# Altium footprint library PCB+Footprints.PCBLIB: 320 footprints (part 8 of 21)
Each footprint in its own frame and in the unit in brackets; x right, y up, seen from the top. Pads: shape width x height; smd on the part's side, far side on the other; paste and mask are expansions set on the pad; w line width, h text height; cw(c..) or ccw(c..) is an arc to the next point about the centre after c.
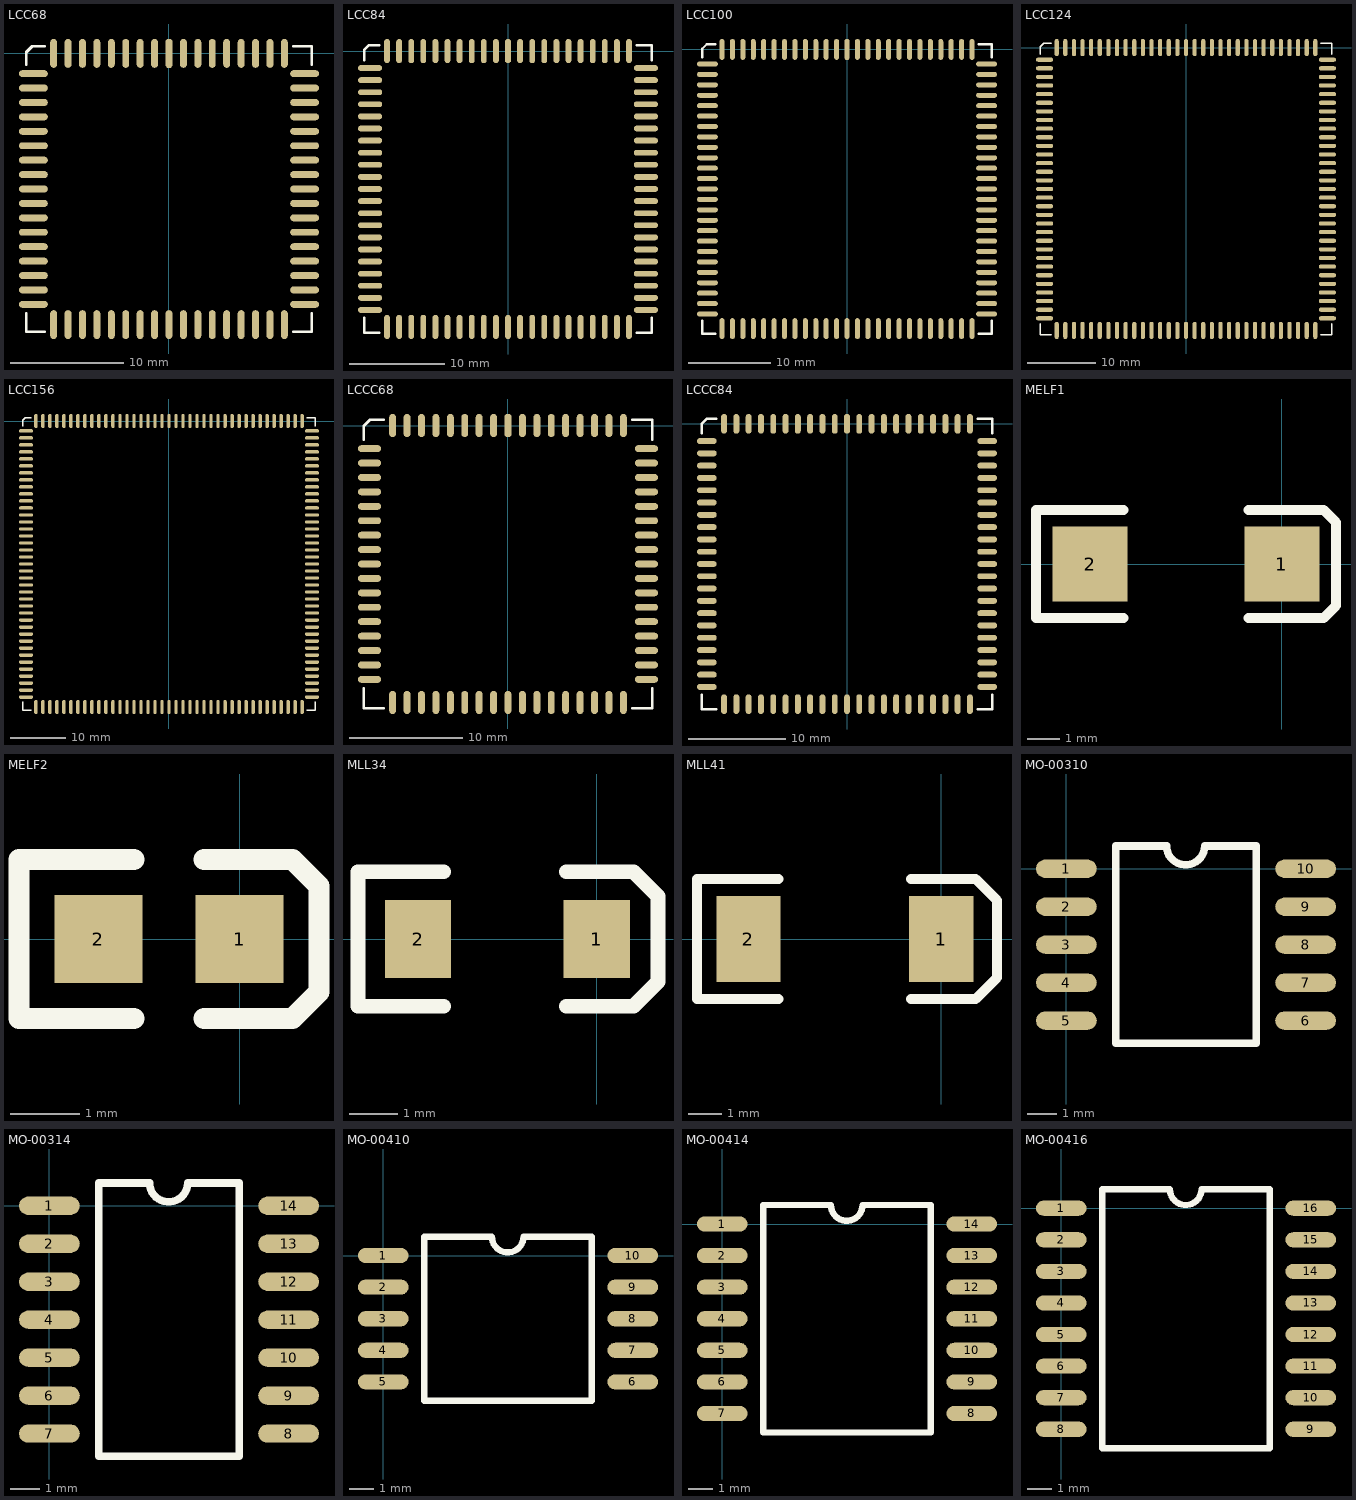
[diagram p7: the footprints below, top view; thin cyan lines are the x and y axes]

## LCC68 [mil]
pads (68):
  oct 24x100 smd: 1(0,0)
  oval 24x100 smd: 2(-50,0) 3(-100,0) 4(-150,0) 5(-200,0) 6(-250,0) 7(-300,0) 8(-350,0) 9(-400,0) 27(-400,-940) 28(-350,-940) 29(-300,-940) 30(-250,-940) 31(-200,-940) 32(-150,-940) 33(-100,-940) 34(-50,-940) 35(0,-940) 36(50,-940) 37(100,-940) 38(150,-940) 39(200,-940) 40(250,-940) 41(300,-940) 42(350,-940) 43(400,-940) 61(400,0) 62(350,0) 63(300,0) 64(250,0) 65(200,0) 66(150,0) 67(100,0) 68(50,0)
  oval 100x24 smd: 10(-470,-70) 11(-470,-120) 12(-470,-170) 13(-470,-220) 14(-470,-270) 15(-470,-320) 16(-470,-370) 17(-470,-420) 18(-470,-470) 19(-470,-520) 20(-470,-570) 21(-470,-620) 22(-470,-670) 23(-470,-720) 24(-470,-770) 25(-470,-820) 26(-470,-870) 44(470,-870) 45(470,-820) 46(470,-770) 47(470,-720) 48(470,-670) 49(470,-620) 50(470,-570) 51(470,-520) 52(470,-470) 53(470,-420) 54(470,-370) 55(470,-320) 56(470,-270) 57(470,-220) 58(470,-170) 59(470,-120) 60(470,-70)
TopOverlay:
  lines w10: -495,-902 -495,-965 -432,-965 ; -495,-38 -495,4 -474,25 -432,25 ; 432,-965 495,-965 495,-902 ; 432,25 495,25 495,-38

## LCC84 [mil]
pads (84):
  oct 24x100 smd: 1(0,0)
  oval 24x100 smd: 2(-50,0) 3(-100,0) 4(-150,0) 5(-200,0) 6(-250,0) 7(-300,0) 8(-350,0) 9(-400,0) 10(-450,0) 11(-500,0) 33(-500,-1140) 34(-450,-1140) 35(-400,-1140) 36(-350,-1140) 37(-300,-1140) 38(-250,-1140) 39(-200,-1140) 40(-150,-1140) 41(-100,-1140) 42(-50,-1140) 43(0,-1140) 44(50,-1140) 45(100,-1140) 46(150,-1140) 47(200,-1140) 48(250,-1140) 49(300,-1140) 50(350,-1140) 51(400,-1140) 52(450,-1140) 53(500,-1140) 75(500,0) 76(450,0) 77(400,0) 78(350,0) 79(300,0) 80(250,0) 81(200,0) 82(150,0) 83(100,0) 84(50,0)
  oval 100x24 smd: 12(-570,-70) 13(-570,-120) 14(-570,-170) 15(-570,-220) 16(-570,-270) 17(-570,-320) 18(-570,-370) 19(-570,-420) 20(-570,-470) 21(-570,-520) 22(-570,-570) 23(-570,-620) 24(-570,-670) 25(-570,-720) 26(-570,-770) 27(-570,-820) 28(-570,-870) 29(-570,-920) 30(-570,-970) 31(-570,-1020) 32(-570,-1070) 54(570,-1070) 55(570,-1020) 56(570,-970) 57(570,-920) 58(570,-870) 59(570,-820) 60(570,-770) 61(570,-720) 62(570,-670) 63(570,-620) 64(570,-570) 65(570,-520) 66(570,-470) 67(570,-420) 68(570,-370) 69(570,-320) 70(570,-270) 71(570,-220) 72(570,-170) 73(570,-120) 74(570,-70)
TopOverlay:
  lines w10: -595,-1102 -595,-1165 -532,-1165 ; -595,-38 -595,4 -574,25 -532,25 ; 532,-1165 595,-1165 595,-1102 ; 532,25 595,25 595,-38

## LCC100 [mil]
pads (100):
  oct 24x100 smd: 1(0,0)
  oval 24x100 smd: 2(-50,0) 3(-100,0) 4(-150,0) 5(-200,0) 6(-250,0) 7(-300,0) 8(-350,0) 9(-400,0) 10(-450,0) 11(-500,0) 12(-550,0) 13(-600,0) 39(-600,-1340) 40(-550,-1340) 41(-500,-1340) 42(-450,-1340) 43(-400,-1340) 44(-350,-1340) 45(-300,-1340) 46(-250,-1340) 47(-200,-1340) 48(-150,-1340) 49(-100,-1340) 50(-50,-1340) 51(0,-1340) 52(50,-1340) 53(100,-1340) 54(150,-1340) 55(200,-1340) 56(250,-1340) 57(300,-1340) 58(350,-1340) 59(400,-1340) 60(450,-1340) 61(500,-1340) 62(550,-1340) 63(600,-1340) 89(600,0) 90(550,0) 91(500,0) 92(450,0) 93(400,0) 94(350,0) 95(300,0) 96(250,0) 97(200,0) 98(150,0) 99(100,0) 100(50,0)
  oval 100x24 smd: 14(-670,-70) 15(-670,-120) 16(-670,-170) 17(-670,-220) 18(-670,-270) 19(-670,-320) 20(-670,-370) 21(-670,-420) 22(-670,-470) 23(-670,-520) 24(-670,-570) 25(-670,-620) 26(-670,-670) 27(-670,-720) 28(-670,-770) 29(-670,-820) 30(-670,-870) 31(-670,-920) 32(-670,-970) 33(-670,-1020) 34(-670,-1070) 35(-670,-1120) 36(-670,-1170) 37(-670,-1220) 38(-670,-1270) 64(670,-1270) 65(670,-1220) 66(670,-1170) 67(670,-1120) 68(670,-1070) 69(670,-1020) 70(670,-970) 71(670,-920) 72(670,-870) 73(670,-820) 74(670,-770) 75(670,-720) 76(670,-670) 77(670,-620) 78(670,-570) 79(670,-520) 80(670,-470) 81(670,-420) 82(670,-370) 83(670,-320) 84(670,-270) 85(670,-220) 86(670,-170) 87(670,-120) 88(670,-70)
TopOverlay:
  lines w10: -695,-1302 -695,-1365 -632,-1365 ; -695,-38 -695,4 -674,25 -632,25 ; 632,-1365 695,-1365 695,-1302 ; 632,25 695,25 695,-38

## LCC124 [mil]
pads (124):
  oct 24x100 smd: 1(0,0)
  oval 24x100 smd: 2(-50,0) 3(-100,0) 4(-150,0) 5(-200,0) 6(-250,0) 7(-300,0) 8(-350,0) 9(-400,0) 10(-450,0) 11(-500,0) 12(-550,0) 13(-600,0) 14(-650,0) 15(-700,0) 16(-750,0) 48(-750,-1640) 49(-700,-1640) 50(-650,-1640) 51(-600,-1640) 52(-550,-1640) 53(-500,-1640) 54(-450,-1640) 55(-400,-1640) 56(-350,-1640) 57(-300,-1640) 58(-250,-1640) 59(-200,-1640) 60(-150,-1640) 61(-100,-1640) 62(-50,-1640) 63(0,-1640) 64(50,-1640) 65(100,-1640) 66(150,-1640) 67(200,-1640) 68(250,-1640) 69(300,-1640) 70(350,-1640) 71(400,-1640) 72(450,-1640) 73(500,-1640) 74(550,-1640) 75(600,-1640) 76(650,-1640) 77(700,-1640) 78(750,-1640) 110(750,0) 111(700,0) 112(650,0) 113(600,0) 114(550,0) 115(500,0) 116(450,0) 117(400,0) 118(350,0) 119(300,0) 120(250,0) 121(200,0) 122(150,0) 123(100,0) 124(50,0)
  oval 100x24 smd: 17(-820,-70) 18(-820,-120) 19(-820,-170) 20(-820,-220) 21(-820,-270) 22(-820,-320) 23(-820,-370) 24(-820,-420) 25(-820,-470) 26(-820,-520) 27(-820,-570) 28(-820,-620) 29(-820,-670) 30(-820,-720) 31(-820,-770) 32(-820,-820) 33(-820,-870) 34(-820,-920) 35(-820,-970) 36(-820,-1020) 37(-820,-1070) 38(-820,-1120) 39(-820,-1170) 40(-820,-1220) 41(-820,-1270) 42(-820,-1320) 43(-820,-1370) 44(-820,-1420) 45(-820,-1470) 46(-820,-1520) 47(-820,-1570) 79(820,-1570) 80(820,-1520) 81(820,-1470) 82(820,-1420) 83(820,-1370) 84(820,-1320) 85(820,-1270) 86(820,-1220) 87(820,-1170) 88(820,-1120) 89(820,-1070) 90(820,-1020) 91(820,-970) 92(820,-920) 93(820,-870) 94(820,-820) 95(820,-770) 96(820,-720) 97(820,-670) 98(820,-620) 99(820,-570) 100(820,-520) 101(820,-470) 102(820,-420) 103(820,-370) 104(820,-320) 105(820,-270) 106(820,-220) 107(820,-170) 108(820,-120) 109(820,-70)
TopOverlay:
  lines w10: -845,-1602 -845,-1665 -782,-1665 ; -845,-38 -845,4 -824,25 -782,25 ; 782,-1665 845,-1665 845,-1602 ; 782,25 845,25 845,-38

## LCC156 [mil]
pads (156):
  oct 24x100 smd: 1(0,0)
  oval 24x100 smd: 2(-50,0) 3(-100,0) 4(-150,0) 5(-200,0) 6(-250,0) 7(-300,0) 8(-350,0) 9(-400,0) 10(-450,0) 11(-500,0) 12(-550,0) 13(-600,0) 14(-650,0) 15(-700,0) 16(-750,0) 17(-800,0) 18(-850,0) 19(-900,0) 20(-950,0) 60(-950,-2040) 61(-900,-2040) 62(-850,-2040) 63(-800,-2040) 64(-750,-2040) 65(-700,-2040) 66(-650,-2040) 67(-600,-2040) 68(-550,-2040) 69(-500,-2040) 70(-450,-2040) 71(-400,-2040) 72(-350,-2040) 73(-300,-2040) 74(-250,-2040) 75(-200,-2040) 76(-150,-2040) 77(-100,-2040) 78(-50,-2040) 79(0,-2040) 80(50,-2040) 81(100,-2040) 82(150,-2040) 83(200,-2040) 84(250,-2040) 85(300,-2040) 86(350,-2040) 87(400,-2040) 88(450,-2040) 89(500,-2040) 90(550,-2040) 91(600,-2040) 92(650,-2040) 93(700,-2040) 94(750,-2040) 95(800,-2040) 96(850,-2040) 97(900,-2040) 98(950,-2040) 138(950,0) 139(900,0) 140(850,0) 141(800,0) 142(750,0) 143(700,0) 144(650,0) 145(600,0) 146(550,0) 147(500,0) 148(450,0) 149(400,0) 150(350,0) 151(300,0) 152(250,0) 153(200,0) 154(150,0) 155(100,0) 156(50,0)
  oval 100x24 smd: 21(-1020,-70) 22(-1020,-120) 23(-1020,-170) 24(-1020,-220) 25(-1020,-270) 26(-1020,-320) 27(-1020,-370) 28(-1020,-420) 29(-1020,-470) 30(-1020,-520) 31(-1020,-570) 32(-1020,-620) 33(-1020,-670) 34(-1020,-720) 35(-1020,-770) 36(-1020,-820) 37(-1020,-870) 38(-1020,-920) 39(-1020,-970) 40(-1020,-1020) 41(-1020,-1070) 42(-1020,-1120) 43(-1020,-1170) 44(-1020,-1220) 45(-1020,-1270) 46(-1020,-1320) 47(-1020,-1370) 48(-1020,-1420) 49(-1020,-1470) 50(-1020,-1520) 51(-1020,-1570) 52(-1020,-1620) 53(-1020,-1670) 54(-1020,-1720) 55(-1020,-1770) 56(-1020,-1820) 57(-1020,-1870) 58(-1020,-1920) 59(-1020,-1970) 99(1020,-1970) 100(1020,-1920) 101(1020,-1870) 102(1020,-1820) 103(1020,-1770) 104(1020,-1720) 105(1020,-1670) 106(1020,-1620) 107(1020,-1570) 108(1020,-1520) 109(1020,-1470) 110(1020,-1420) 111(1020,-1370) 112(1020,-1320) 113(1020,-1270) 114(1020,-1220) 115(1020,-1170) 116(1020,-1120) 117(1020,-1070) 118(1020,-1020) 119(1020,-970) 120(1020,-920) 121(1020,-870) 122(1020,-820) 123(1020,-770) 124(1020,-720) 125(1020,-670) 126(1020,-620) 127(1020,-570) 128(1020,-520) 129(1020,-470) 130(1020,-420) 131(1020,-370) 132(1020,-320) 133(1020,-270) 134(1020,-220) 135(1020,-170) 136(1020,-120) 137(1020,-70)
TopOverlay:
  lines w10: -1045,-2002 -1045,-2065 -982,-2065 ; -1045,-38 -1045,4 -1024,25 -982,25 ; 982,-2065 1045,-2065 1045,-2002 ; 982,25 1045,25 1045,-38

## LCCC68 [mil]
pads (68):
  oct 24x80 smd: 1(0,0)
  oval 24x80 smd: 2(-50,0) 3(-100,0) 4(-150,0) 5(-200,0) 6(-250,0) 7(-300,0) 8(-350,0) 9(-400,0) 27(-400,-960) 28(-350,-960) 29(-300,-960) 30(-250,-960) 31(-200,-960) 32(-150,-960) 33(-100,-960) 34(-50,-960) 35(0,-960) 36(50,-960) 37(100,-960) 38(150,-960) 39(200,-960) 40(250,-960) 41(300,-960) 42(350,-960) 43(400,-960) 61(400,0) 62(350,0) 63(300,0) 64(250,0) 65(200,0) 66(150,0) 67(100,0) 68(50,0)
  oval 80x24 smd: 10(-480,-80) 11(-480,-130) 12(-480,-180) 13(-480,-230) 14(-480,-280) 15(-480,-330) 16(-480,-380) 17(-480,-430) 18(-480,-480) 19(-480,-530) 20(-480,-580) 21(-480,-630) 22(-480,-680) 23(-480,-730) 24(-480,-780) 25(-480,-830) 26(-480,-880) 44(480,-880) 45(480,-830) 46(480,-780) 47(480,-730) 48(480,-680) 49(480,-630) 50(480,-580) 51(480,-530) 52(480,-480) 53(480,-430) 54(480,-380) 55(480,-330) 56(480,-280) 57(480,-230) 58(480,-180) 59(480,-130) 60(480,-80)
TopOverlay:
  lines w10: -500,-912 -500,-980 -432,-980 ; -500,-48 -500,-2 -478,20 -432,20 ; 432,-980 500,-980 500,-912 ; 432,20 500,20 500,-48

## LCCC84 [mil]
pads (84):
  oct 24x80 smd: 1(0,0)
  oval 24x80 smd: 2(-50,0) 3(-100,0) 4(-150,0) 5(-200,0) 6(-250,0) 7(-300,0) 8(-350,0) 9(-400,0) 10(-450,0) 11(-500,0) 33(-500,-1140) 34(-450,-1140) 35(-400,-1140) 36(-350,-1140) 37(-300,-1140) 38(-250,-1140) 39(-200,-1140) 40(-150,-1140) 41(-100,-1140) 42(-50,-1140) 43(0,-1140) 44(50,-1140) 45(100,-1140) 46(150,-1140) 47(200,-1140) 48(250,-1140) 49(300,-1140) 50(350,-1140) 51(400,-1140) 52(450,-1140) 53(500,-1140) 75(500,0) 76(450,0) 77(400,0) 78(350,0) 79(300,0) 80(250,0) 81(200,0) 82(150,0) 83(100,0) 84(50,0)
  oval 80x24 smd: 12(-570,-70) 13(-570,-120) 14(-570,-170) 15(-570,-220) 16(-570,-270) 17(-570,-320) 18(-570,-370) 19(-570,-420) 20(-570,-470) 21(-570,-520) 22(-570,-570) 23(-570,-620) 24(-570,-670) 25(-570,-720) 26(-570,-770) 27(-570,-820) 28(-570,-870) 29(-570,-920) 30(-570,-970) 31(-570,-1020) 32(-570,-1070) 54(570,-1070) 55(570,-1020) 56(570,-970) 57(570,-920) 58(570,-870) 59(570,-820) 60(570,-770) 61(570,-720) 62(570,-670) 63(570,-620) 64(570,-570) 65(570,-520) 66(570,-470) 67(570,-420) 68(570,-370) 69(570,-320) 70(570,-270) 71(570,-220) 72(570,-170) 73(570,-120) 74(570,-70)
TopOverlay:
  lines w10: -590,-1102 -590,-1160 -532,-1160 ; -590,-38 -590,1 -571,20 -532,20 ; 532,-1160 590,-1160 590,-1102 ; 532,20 590,20 590,-38

## MELF1 [mil]
pads (2):
  rect 90x90 smd: 1(0,0) 2(-230,0)
TopOverlay:
  lines w12: -190,-65 -295,-65 -295,65 -190,65 ; -40,-65 50,-65 65,-50 65,50 50,65 -40,65

## MELF2 [mil]
pads (2):
  rect 50x50 smd: 1(0,0) 2(-80,0)
TopOverlay:
  lines w12: -60,-45 -125,-45 -125,45 -60,45 ; -20,-45 30,-45 45,-30 45,30 30,45 -20,45

## MLL34 [mil]
pads (2):
  rect 54x64 smd: 1(0,0) 2(-146,0)
TopOverlay:
  lines w12: -125,-55 -195,-55 -195,55 -125,55 ; -25,-55 30,-55 50,-35 50,35 30,55 -25,55

## MLL41 [mil]
pads (2):
  rect 75x100 smd: 1(0,0) 2(-225,0)
TopOverlay:
  lines w12: -190,-70 -285,-70 -285,70 -190,70 ; -35,-70 40,-70 65,-45 65,45 40,70 -35,70

## MO-00310 [mil]
pads (10):
  oval 80x24 smd: 1(0,0) 2(0,-50) 3(0,-100) 4(0,-150) 5(0,-200) 6(315,-200) 7(315,-150) 8(315,-100) 9(315,-50) 10(315,0)
TopOverlay:
  lines w10: 65,-230 250,-230 250,30 182,30 cw(c157,30) 132,30 65,30 65,-230

## MO-00314 [mil]
pads (14):
  oval 80x24 smd: 1(0,0) 2(0,-50) 3(0,-100) 4(0,-150) 5(0,-200) 6(0,-250) 7(0,-300) 8(315,-300) 9(315,-250) 10(315,-200) 11(315,-150) 12(315,-100) 13(315,-50) 14(315,0)
TopOverlay:
  lines w10: 65,-330 250,-330 250,30 182,30 cw(c157,30) 132,30 65,30 65,-330

## MO-00410 [mil]
pads (10):
  oval 80x24 smd: 1(0,0) 2(0,-50) 3(0,-100) 4(0,-150) 5(0,-200) 6(395,-200) 7(395,-150) 8(395,-100) 9(395,-50) 10(395,0)
TopOverlay:
  lines w10: 65,-230 330,-230 330,30 222,30 cw(c197,30) 172,30 65,30 65,-230

## MO-00414 [mil]
pads (14):
  oval 80x24 smd: 1(0,0) 2(0,-50) 3(0,-100) 4(0,-150) 5(0,-200) 6(0,-250) 7(0,-300) 8(395,-300) 9(395,-250) 10(395,-200) 11(395,-150) 12(395,-100) 13(395,-50) 14(395,0)
TopOverlay:
  lines w10: 65,-330 330,-330 330,30 222,30 cw(c197,30) 172,30 65,30 65,-330

## MO-00416 [mil]
pads (16):
  oval 80x24 smd: 1(0,0) 2(0,-50) 3(0,-100) 4(0,-150) 5(0,-200) 6(0,-250) 7(0,-300) 8(0,-350) 9(395,-350) 10(395,-300) 11(395,-250) 12(395,-200) 13(395,-150) 14(395,-100) 15(395,-50) 16(395,0)
TopOverlay:
  lines w10: 65,-380 330,-380 330,30 222,30 cw(c197,30) 172,30 65,30 65,-380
